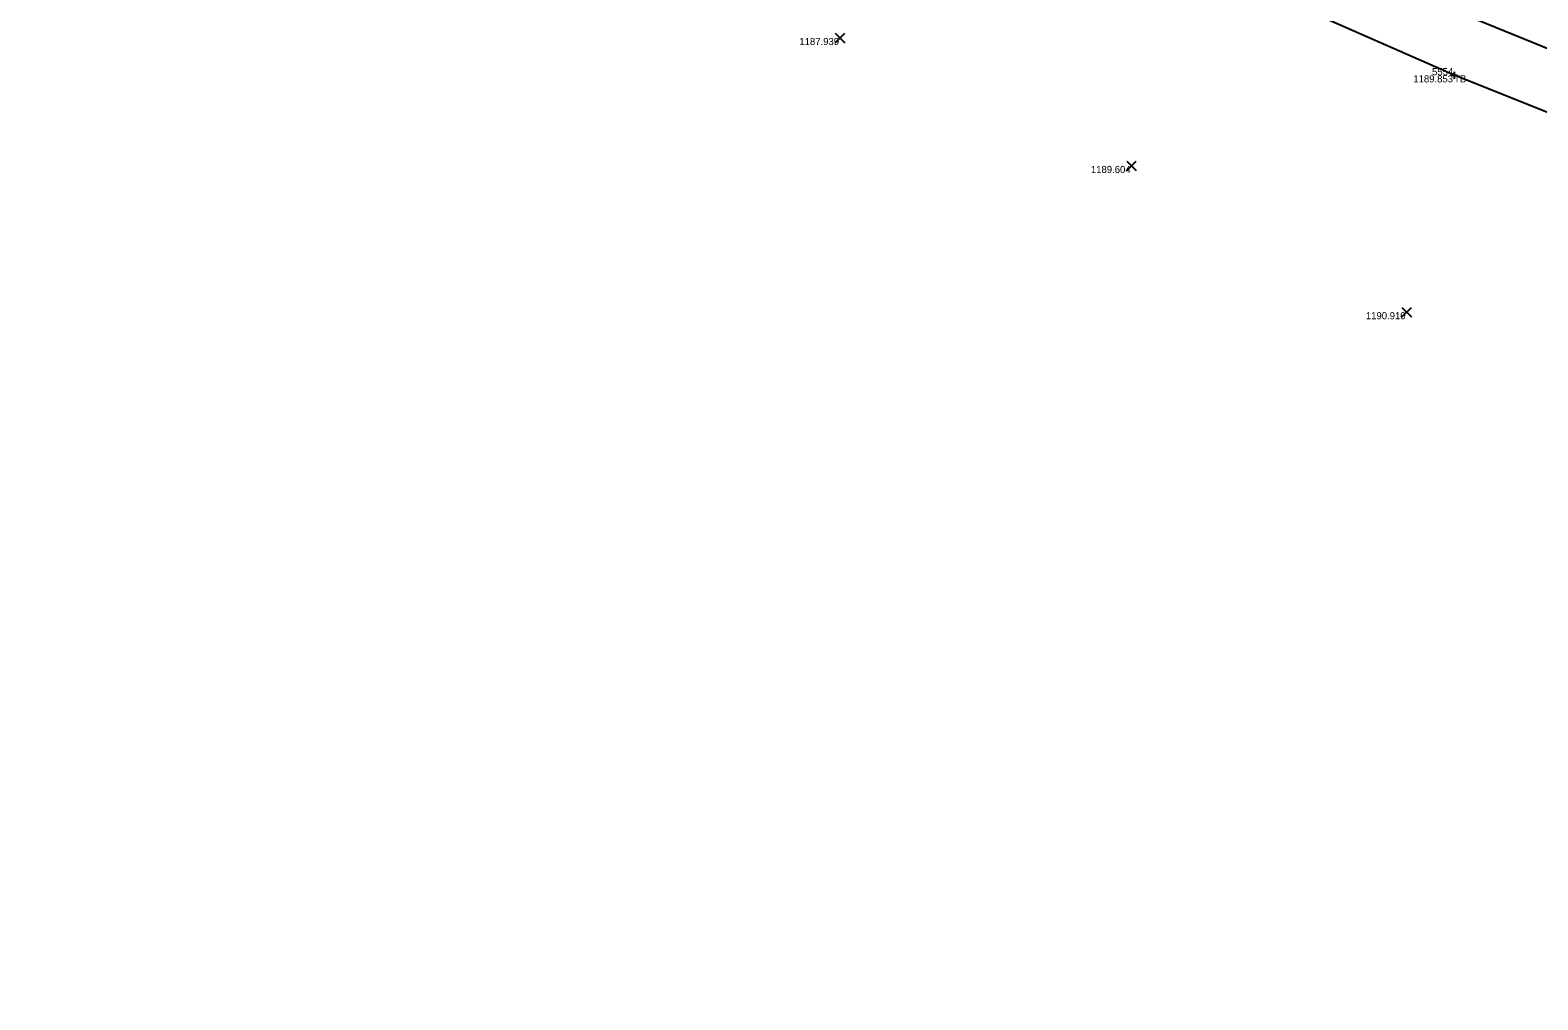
# Model space of a CAD drawing. Extents: x 2044996 to 2050343, y 455232 to 458054.
# Drawn here: x 2046987 to 2047198.7, y 457001.7 to 457137.8 of the extents above; entities that cross this region are included whole.
import ezdxf

# ---------------------------------------------------------------- set-up
doc = ezdxf.new("R2010")
doc.units = 0
for name, color, linetype in [('DR_X_Ditch', 7, 'Continuous'), ('DT_X_Contour_Minor', 7, 'Continuous'), ('DT_X_Contour_Text', 7, 'Continuous'), ('DT_X_Spot_Elev', 7, 'Continuous'), ('DT_X_Triangles', 7, 'Continuous'), ('DT_X_Void', 7, 'Continuous'), ('SV_X_Top_of_Bank', 7, 'Continuous')]:
    doc.layers.add(name, color=color, linetype=linetype)

msp = doc.modelspace()

# ---------------------------------------------------------------- linework, layer by layer
at = {"layer": 'DR_X_Ditch'}
msp.add_lwpolyline([(2047543.3, 457005.16), (2047510.9, 457017.43), (2047468.96, 457033.16), (2047427.45, 457048.41), (2047415.45, 457054.04), (2047370.9, 457068.47), (2047328.33, 457085.8), (2047280.45, 457104.21), (2047241.61, 457118.3), (2047187.46, 457140.33), (2047142.69, 457158.87), (2047125.5, 457162.21), (2047087.92, 457177.75), (2047044.55, 457195.18), (2046997.32, 457212.04), (2046988.97, 457212.79)], dxfattribs=at)
at = {"layer": 'DT_X_Spot_Elev'}
for p, q in [((2047100.05, 457136.03), (2047101.39, 457137.37)), ((2047100.05, 457137.37), (2047101.39, 457136.03)), ((2047140.98, 457118.08), (2047142.31, 457119.42)), ((2047140.98, 457119.42), (2047142.31, 457118.08)), ((2047179.61, 457097.57), (2047180.94, 457098.9)), ((2047179.61, 457098.9), (2047180.94, 457097.57))]:
    msp.add_line(p, q, dxfattribs=at)
at = {"layer": 'DT_X_Void'}
for p, q in [((2047186.42, 457131.46), (2047187.42, 457131.46)), ((2047186.92, 457131.96), (2047186.92, 457130.96)), ((2047186.92, 457131.46), (2047186.92, 457131.46))]:
    msp.add_line(p, q, dxfattribs=at)
at = {"layer": 'SV_X_Top_of_Bank'}
msp.add_lwpolyline([(2047542.15, 457001.74), (2047509.52, 457012.3), (2047466.73, 457029.21), (2047424.59, 457044.27), (2047411.67, 457048.03), (2047368.41, 457063.9), (2047324.9, 457081.08), (2047276.68, 457098.42), (2047234.84, 457112.37), (2047186.92, 457131.46), (2047138.32, 457152.85), (2047124.48, 457159.14), (2047084.84, 457174.36), (2047041.82, 457189.99), (2046999.84, 457207.19), (2046987.02, 457211.13)], dxfattribs=at)

# ---------------------------------------------------------------- texts
at = {"layer": 'DT_X_Contour_Minor'}
for s, p in [('1187.939', (2047095.01, 457135.7)), ('1189.853', (2047181.2, 457130.46)), ('1189.604', (2047135.94, 457117.75)), ('1190.910', (2047174.54, 457097.23))]:
    msp.add_text(s, height=1, dxfattribs=at).set_placement(p)
at = {"layer": 'DT_X_Contour_Text'}
msp.add_text('TB', height=1, dxfattribs=at).set_placement((2047186.92, 457130.46))
at = {"layer": 'DT_X_Triangles'}
msp.add_text('5554', height=1, dxfattribs=at).set_placement((2047183.83, 457131.46))

doc.saveas('drawing.dxf')
